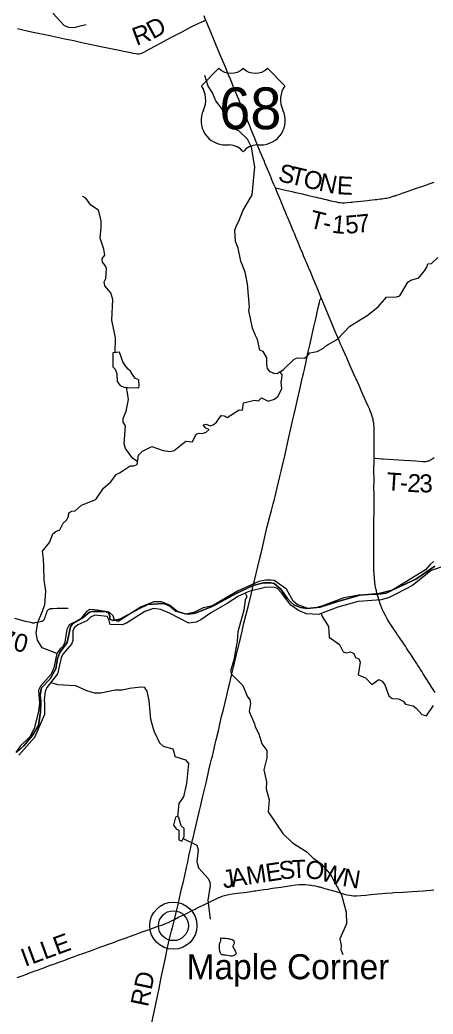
# Model space of a CAD drawing. Extents: x 1410790 to 1770854, y 448063 to 770588.
# Drawn here: x 1569641 to 1576526, y 587397 to 603957 of the extents above; entities that cross this region are included whole.
import ezdxf

# ---------------------------------------------------------------- set-up
doc = ezdxf.new("R2010")
doc.units = 0
for name, color, linetype in [('GM_X_County_Road', 7, 'Continuous'), ('GM_X_County_Road_Text', 7, 'Continuous'), ('GM_X_Major_River', 7, 'Continuous'), ('GM_X_Minor_Lake', 7, 'Continuous'), ('GM_X_Minor_River', 7, 'Continuous'), ('GM_X_Township', 7, 'Continuous'), ('GM_X_Township_Road', 7, 'Continuous'), ('GM_X_Township_Road_Text', 7, 'Continuous'), ('GM_X_Unincorporated', 7, 'Continuous'), ('GM_X_Unincorporated_Location', 7, 'Continuous'), ('GM_X_Unincorporated_Text', 7, 'Continuous'), ('GM_X_US_Location', 7, 'Continuous'), ('GM_X_US_Route', 7, 'Continuous'), ('GM_X_US_Shield', 7, 'Continuous')]:
    doc.layers.add(name, color=color, linetype=linetype)

msp = doc.modelspace()

# ---------------------------------------------------------------- linework, layer by layer
at = {"layer": 'GM_X_County_Road'}
for points in [[(1573528, 594535), (1573554, 594641), (1573605, 594855), (1573640, 594991), (1573660, 595077), (1573693, 595221), (1573724, 595348), (1573764, 595520), (1573806, 595684), (1573832, 595785), (1573861, 595899), (1573881, 595975), (1573892, 596020), (1573927, 596162), (1573971, 596353), (1573992, 596443), (1574014, 596536), (1574059, 596721), (1574123, 597007), (1574154, 597154), (1574189, 597303), (1574210, 597389), (1574232, 597485), (1574265, 597636), (1574298, 597779), (1574350, 598006), (1574364, 598067), (1574381, 598136), (1574412, 598270), (1574430, 598350), (1574447, 598431), (1574475, 598559), (1574518, 598744), (1574540, 598843), (1574555, 598910), (1574571, 598980), (1574586, 599051), (1574589, 599064), (1574606, 599140), (1574617, 599188), (1574631, 599252), (1574641, 599290), (1574645, 599300), (1574648, 599308), (1574661, 599330)], [(1572217, 588976), (1572255, 589133), (1572271, 589199), (1572283, 589252), (1572336, 589482), (1572361, 589584), (1572389, 589705), (1572419, 589840), (1572437, 589926), (1572457, 590029), (1572473, 590101), (1572482, 590142), (1572490, 590176), (1572519, 590301), (1572533, 590355), (1572552, 590434), (1572581, 590552), (1572636, 590788), (1572656, 590878), (1572684, 591006), (1572744, 591251), (1572774, 591378), (1572792, 591462), (1572813, 591554), (1572835, 591643), (1572848, 591694), (1572896, 591899), (1572912, 591966), (1572948, 592116), (1572974, 592227), (1573003, 592352), (1573031, 592473), (1573087, 592706), (1573112, 592807), (1573137, 592915), (1573173, 593066), (1573205, 593197), (1573245, 593363), (1573300, 593593), (1573315, 593656), (1573354, 593823), (1573369, 593886), (1573407, 594036), (1573448, 594205), (1573492, 594386), (1573528, 594535)], [(1572217, 588976), (1572238, 588988), (1572258, 588998), (1572284, 589012), (1572355, 589047), (1572426, 589081), (1572488, 589111), (1572521, 589126), (1572559, 589144), (1572580, 589155), (1572603, 589166), (1572726, 589227), (1572788, 589258), (1572838, 589283), (1572876, 589302), (1572888, 589307), (1572911, 589319), (1572934, 589329), (1572946, 589335), (1572976, 589347), (1573013, 589360), (1573051, 589371), (1573099, 589383), (1573147, 589393), (1573183, 589398), (1573264, 589410), (1573372, 589423), (1573462, 589436), (1573543, 589448), (1573553, 589450), (1573572, 589453), (1573631, 589461), (1573705, 589472), (1573770, 589481), (1573816, 589487), (1573851, 589493), (1573987, 589514), (1574159, 589540), (1574234, 589549), (1574293, 589554), (1574346, 589556), (1574396, 589555), (1574445, 589552), (1574484, 589547), (1574494, 589545), (1574517, 589542), (1574565, 589532), (1574603, 589523), (1574616, 589520), (1574638, 589515), (1574721, 589492), (1574765, 589480), (1574781, 589475), (1574828, 589461), (1574910, 589437), (1574960, 589422), (1575045, 589397), (1575089, 589386), (1575137, 589376), (1575166, 589372), (1575202, 589369), (1575247, 589369), (1575319, 589372), (1575407, 589380), (1575488, 589388), (1575603, 589399), (1575674, 589405), (1575730, 589410), (1575844, 589419), (1575867, 589421), (1576021, 589431), (1576175, 589441), (1576368, 589453), (1576424, 589457), (1576492, 589463), (1576537, 589470)], [(1569599, 588007), (1569679, 588037), (1569740, 588059), (1569777, 588072), (1569820, 588088), (1569913, 588122), (1569953, 588136), (1569977, 588145), (1570005, 588155), (1570038, 588168), (1570081, 588185), (1570118, 588199), (1570164, 588216), (1570188, 588225), (1570253, 588248), (1570290, 588261), (1570340, 588279), (1570361, 588287), (1570389, 588297), (1570459, 588324), (1570520, 588347), (1570635, 588388), (1570672, 588401), (1570833, 588458), (1570974, 588510), (1571024, 588528), (1571061, 588541), (1571101, 588556), (1571199, 588592), (1571279, 588622), (1571312, 588635), (1571427, 588675), (1571442, 588681), (1571470, 588690), (1571581, 588730), (1571664, 588760), (1571745, 588789), (1571831, 588819), (1571868, 588833), (1571945, 588860), (1572016, 588886), (1572035, 588892), (1572095, 588916), (1572116, 588925), (1572158, 588944), (1572217, 588976)], [(1571481, 585543), (1571507, 585661), (1571561, 585919), (1571597, 586089), (1571640, 586288), (1571674, 586448), (1571687, 586509), (1571756, 586843), (1571805, 587077), (1571836, 587228), (1571874, 587408), (1571928, 587669), (1571960, 587823), (1571998, 588006), (1572061, 588308), (1572103, 588507), (1572134, 588649), (1572167, 588786), (1572187, 588861), (1572199, 588908), (1572217, 588976)]]:
    msp.add_lwpolyline(points, dxfattribs=at)
at = {"layer": 'GM_X_Major_River'}
for points in [[(1576471, 594881), (1576397, 594797), (1575812, 594437), (1575737, 594404), (1575608, 594387), (1575291, 594375), (1575037, 594330), (1574671, 594194), (1574566, 594165), (1574441, 594153), (1574262, 594222), (1574197, 594277), (1574085, 594473), (1573876, 594620), (1573822, 594627), (1573741, 594627), (1573622, 594604), (1573269, 594441), (1572905, 594231), (1572830, 594190), (1572693, 594164), (1572549, 594093), (1572410, 594058), (1572266, 594105), (1572136, 594208), (1572001, 594264), (1571872, 594265), (1571662, 594183), (1571279, 593939), (1571219, 593961), (1571195, 594031), (1571128, 594091), (1570928, 594128), (1570878, 594133), (1570806, 594139), (1570755, 594110), (1570647, 593968), (1570461, 593882), (1570423, 593804), (1570388, 593595), (1570362, 593525), (1570307, 593476), (1570257, 593401), (1570207, 593165), (1570161, 593058), (1569983, 592857), (1569954, 592794), (1569967, 592575), (1569950, 592441), (1569930, 592347), (1569877, 592153), (1569810, 592018), (1569645, 591860), (1569573, 591753)], [(1576754, 594876), (1576495, 594786), (1576184, 594535), (1575906, 594393), (1575782, 594333), (1575659, 594300), (1575279, 594271), (1574941, 594174), (1574619, 594055), (1574419, 594064), (1574282, 594119), (1574153, 594210), (1573999, 594414), (1573935, 594484), (1573865, 594508), (1573730, 594501), (1573458, 594437), (1573284, 594361), (1573096, 594239), (1573019, 594192), (1572836, 594088), (1572656, 593962), (1572579, 593923), (1572456, 593910), (1572135, 594074), (1571990, 594138), (1571870, 594152), (1571724, 594104), (1571415, 593910), (1571346, 593882), (1571147, 593886), (1571131, 593955), (1571098, 594022), (1570890, 594043), (1570819, 594008), (1570755, 593947), (1570609, 593880), (1570544, 593834), (1570523, 593782), (1570525, 593621), (1570501, 593560), (1570359, 593394), (1570330, 593331), (1570269, 593063), (1570091, 592839), (1570060, 592769), (1570048, 592629), (1570051, 592579), (1570051, 592386), (1569883, 592003), (1569622, 591708)], [(1576535, 594937), (1576470, 594880)]]:
    msp.add_lwpolyline(points, dxfattribs=at)
at = {"layer": 'GM_X_Minor_Lake'}
for points in [[(1571626, 597863), (1571624, 597960), (1571568, 597983), (1571538, 598015), (1571519, 598052), (1571486, 598106), (1571448, 598137), (1571399, 598196), (1571356, 598263), (1571337, 598330), (1571301, 598424), (1571190, 598412), (1571190, 598176), (1571230, 598137), (1571259, 598064), (1571264, 597932), (1571311, 597865), (1571371, 597840), (1571435, 597835)], [(1571435, 597835), (1571621, 597827), (1571626, 597863)], [(1572235, 590679), (1572198, 590547), (1572245, 590484), (1572287, 590461), (1572292, 590362), (1572289, 590300), (1572341, 590279), (1572379, 590358), (1572381, 590491), (1572328, 590534), (1572308, 590609), (1572289, 590673)], [(1572289, 590673), (1572275, 590685), (1572262, 590691), (1572235, 590679)], [(1572992, 588669), (1573020, 588665), (1573038, 588662), (1573068, 588660), (1573094, 588658), (1573114, 588658), (1573126, 588654), (1573140, 588650), (1573154, 588648), (1573178, 588641), (1573194, 588629), (1573204, 588613), (1573210, 588601), (1573210, 588585), (1573206, 588565), (1573200, 588551), (1573194, 588541), (1573189, 588527), (1573189, 588517), (1573195, 588507), (1573207, 588491), (1573217, 588466), (1573227, 588452), (1573233, 588436), (1573241, 588424), (1573243, 588410), (1573237, 588394), (1573227, 588384), (1573217, 588378), (1573200, 588370), (1573190, 588366), (1573174, 588364), (1573152, 588365), (1573128, 588369), (1573098, 588373), (1573066, 588377), (1573038, 588379), (1573022, 588382), (1573008, 588386), (1572992, 588402), (1572984, 588412), (1572972, 588446), (1572970, 588456), (1572968, 588468), (1572966, 588480), (1572966, 588494), (1572965, 588508), (1572965, 588522), (1572965, 588537), (1572965, 588547), (1572967, 588557), (1572967, 588567), (1572973, 588581), (1572979, 588595), (1572983, 588605), (1572989, 588617), (1572992, 588669)]]:
    msp.add_lwpolyline(points, dxfattribs=at)
at = {"layer": 'GM_X_Minor_River'}
for points in [[(1570190, 604068), (1570379, 603864), (1570449, 603835), (1570551, 603833), (1570668, 603861), (1570745, 603880)], [(1570035, 594973), (1570021, 595110), (1570134, 595250), (1570189, 595396), (1570239, 595437), (1570306, 595464), (1570360, 595575), (1570417, 595625), (1570454, 595688), (1570457, 595744), (1570508, 595775), (1570560, 595780), (1570666, 595875), (1570906, 595969), (1571034, 596157), (1571156, 596264), (1571246, 596384), (1571299, 596415), (1571363, 596454), (1571477, 596531), (1571541, 596530), (1571594, 596549), (1571618, 596707), (1571686, 596772), (1571841, 596853), (1572029, 596786), (1572143, 596766), (1572213, 596787), (1572406, 596938), (1572518, 596932), (1572577, 597057), (1572629, 597074), (1572681, 597067), (1572744, 597090), (1572794, 597136), (1572739, 597155), (1572694, 597212), (1572744, 597223), (1572810, 597196), (1572860, 597211), (1572917, 597256), (1572993, 597367), (1573043, 597364), (1573097, 597337), (1573295, 597464), (1573349, 597459), (1573367, 597579), (1573440, 597596), (1573551, 597622), (1573617, 597611), (1573669, 597660), (1573779, 597606), (1573886, 597640), (1573937, 597687), (1574005, 597811), (1573997, 597927), (1574008, 597979), (1574011, 598043), (1573980, 598096), (1573929, 598063), (1573871, 598066), (1573813, 598093), (1573768, 598152), (1573753, 598216), (1573755, 598328), (1573697, 598433), (1573641, 598458), (1573602, 598634), (1573565, 598700), (1573517, 598822), (1573458, 599115), (1573465, 599173), (1573431, 599563), (1573397, 599758), (1573325, 599938), (1573277, 600155), (1573233, 600268), (1573224, 600455), (1573253, 600530), (1573287, 600604), (1573354, 600775), (1573511, 601043), (1573555, 601512), (1573502, 601837), (1573436, 601971), (1573288, 602112), (1573235, 602133), (1573186, 602198), (1573065, 602290), (1573037, 602431), (1573002, 602487), (1572904, 602609), (1572848, 602745), (1572780, 602854), (1572723, 603030)], [(1571228, 598416), (1571233, 598664), (1571172, 598954), (1571192, 599298), (1571157, 599409), (1571055, 599527), (1571046, 599592), (1571073, 599647), (1571086, 599816), (1571065, 599868), (1571018, 599923), (1571015, 599983), (1571054, 600041), (1571038, 600141), (1570978, 600321), (1570998, 600499), (1570994, 600617), (1570952, 600790), (1570823, 600869), (1570743, 600988), (1570692, 601015), (1570682, 601020)], [(1573980, 598096), (1574036, 598133), (1574212, 598304), (1574264, 598327), (1574383, 598325), (1574433, 598359), (1574470, 598410), (1574593, 598432), (1574700, 598488), (1574751, 598536), (1574931, 598639), (1575141, 598854), (1575425, 599035), (1575610, 599179), (1575747, 599339), (1575916, 599344), (1575970, 599359), (1576104, 599587), (1576155, 599622), (1576288, 599662), (1576380, 599775), (1576419, 599838), (1576436, 599892), (1576498, 599899), (1576606, 600002)], [(1571602, 596603), (1571521, 596652), (1571400, 596817), (1571379, 596897), (1571402, 597196), (1571363, 597256), (1571362, 597317), (1571412, 597440), (1571450, 597632), (1571436, 597744), (1571415, 597836)], [(1570257, 593401), (1570015, 593496), (1569934, 593625), (1569915, 593747), (1569940, 593919), (1570014, 594098), (1570057, 594215), (1570076, 594440), (1570044, 594629), (1570042, 594854), (1570035, 594973)], [(1573396, 594410), (1573424, 594351), (1573394, 594292), (1573375, 594128), (1573275, 593765), (1573263, 593607), (1573207, 593297), (1573149, 593112), (1573172, 593056), (1573358, 592871), (1573426, 592691), (1573473, 592631), (1573484, 592571), (1573461, 592437), (1573553, 592232), (1573559, 592180), (1573625, 592066), (1573670, 591897), (1573755, 591790), (1573756, 591736), (1573755, 591664), (1573706, 591465), (1573748, 591269), (1573744, 591151), (1573792, 590965), (1573780, 590767), (1574022, 590408), (1574181, 590250), (1574421, 590098), (1574526, 589993), (1574590, 589954), (1574653, 589908), (1574815, 589724), (1574998, 589382), (1575080, 589098), (1575082, 588901), (1574971, 588649), (1574996, 588538), (1574987, 588476), (1575021, 588389)], [(1574662, 594071), (1574679, 594019), (1574781, 593856), (1574796, 593677), (1574969, 593555), (1575025, 593433), (1575084, 593414), (1575147, 593429), (1575204, 593403), (1575233, 593338), (1575289, 593315), (1575312, 593262), (1575279, 593050), (1575402, 592999), (1575506, 592885), (1575622, 592972), (1575679, 592941), (1575722, 592882), (1575786, 592698), (1575846, 592652), (1575952, 592650), (1576025, 592612), (1576066, 592561), (1576194, 592530), (1576245, 592494), (1576339, 592386), (1576418, 592364), (1576532, 592536)], [(1570155, 592919), (1570269, 592889), (1570567, 592872), (1570754, 592787), (1570879, 592750), (1570989, 592750), (1571231, 592800), (1571345, 592801), (1571468, 592829), (1571656, 592848), (1571712, 592841), (1571759, 592776), (1571788, 592617), (1571819, 592311), (1571873, 592115), (1571967, 591916), (1572030, 591861), (1572189, 591817), (1572214, 591744), (1572223, 591690), (1572402, 591631), (1572449, 591572), (1572419, 591238), (1572367, 591018), (1572290, 590908), (1572267, 590689)], [(1572362, 590323), (1572588, 590209), (1572610, 590132), (1572588, 589940), (1572618, 589833), (1572772, 589659), (1572805, 589598), (1572814, 589540), (1572773, 589296), (1572810, 588978)]]:
    msp.add_lwpolyline(points, dxfattribs=at)
at = {"layer": 'GM_X_Township'}
for points in [[(1569593, 591763), (1569705, 591867), (1569844, 592030), (1569954, 592204), (1569986, 592431), (1569989, 592601), (1569980, 592715), (1570003, 592830), (1570146, 592983), (1570238, 593149), (1570267, 593317), (1570308, 593421), (1570432, 593585), (1570484, 593849), (1570525, 593901), (1570698, 594002), (1570801, 594091), (1570851, 594105), (1571064, 594103), (1571118, 594079), (1571140, 594027), (1571139, 593976), (1571197, 593952), (1571308, 593977), (1571636, 594153), (1571775, 594218), (1572032, 594238), (1572134, 594195), (1572238, 594110), (1572394, 594067), (1572452, 594058), (1572569, 594075), (1572856, 594194), (1573257, 594411), (1573519, 594533), (1573530, 594536), (1573702, 594580), (1573817, 594579), (1573879, 594567), (1573988, 594478), (1574102, 594318), (1574151, 594266), (1574207, 594217), (1574315, 594170), (1574429, 594153), (1574646, 594173), (1574940, 594269), (1575312, 594377), (1575567, 594399), (1575629, 594404), (1575842, 594461), (1576237, 594642), (1576556, 594859)], [(1576556, 594859), (1576237, 594642), (1575842, 594461), (1575629, 594404), (1575567, 594399), (1575312, 594377), (1574940, 594269), (1574646, 594173), (1574429, 594153), (1574315, 594170), (1574207, 594217), (1574151, 594266), (1574102, 594318), (1573988, 594478), (1573879, 594567), (1573817, 594579), (1573702, 594580), (1573530, 594536), (1573519, 594533), (1573257, 594411), (1572856, 594194), (1572569, 594075), (1572452, 594058), (1572394, 594067), (1572238, 594110), (1572134, 594195), (1572032, 594238), (1571775, 594218), (1571636, 594153), (1571308, 593977), (1571197, 593952), (1571139, 593976), (1571140, 594027), (1571118, 594079), (1571064, 594103), (1570851, 594105), (1570801, 594091), (1570698, 594002), (1570525, 593901), (1570484, 593849), (1570432, 593585), (1570308, 593421), (1570267, 593317), (1570238, 593149), (1570146, 592983), (1570003, 592830), (1569980, 592715), (1569989, 592601), (1569986, 592431), (1569954, 592204), (1569844, 592030), (1569705, 591867), (1569593, 591763)]]:
    msp.add_lwpolyline(points, dxfattribs=at)
at = {"layer": 'GM_X_Township_Road'}
for points in [[(1569602, 603813), (1569691, 603794), (1569837, 603760), (1570055, 603714), (1570141, 603696), (1570393, 603641), (1570538, 603613), (1570676, 603583), (1570833, 603549), (1571016, 603511), (1571186, 603476), (1571484, 603412), (1571526, 603403), (1571571, 603395), (1571598, 603393), (1571628, 603394), (1571655, 603400), (1571683, 603410), (1571716, 603425), (1571794, 603468), (1571911, 603533), (1572045, 603603), (1572158, 603662), (1572344, 603760), (1572495, 603839), (1572592, 603887), (1572633, 603907), (1572662, 603921), (1572698, 603938), (1572736, 603956)], [(1573898, 601158), (1573949, 601147), (1574016, 601133), (1574122, 601109), (1574171, 601098), (1574233, 601084), (1574266, 601077), (1574297, 601070), (1574350, 601058), (1574405, 601045), (1574433, 601039), (1574473, 601029), (1574520, 601018), (1574577, 601003), (1574619, 600993), (1574648, 600986), (1574711, 600971), (1574746, 600963), (1574762, 600959), (1574820, 600946), (1574877, 600933), (1574919, 600924), (1574934, 600920), (1574958, 600916), (1574978, 600913), (1575012, 600911), (1575031, 600910), (1575050, 600911), (1575093, 600913), (1575148, 600919), (1575177, 600923), (1575200, 600925), (1575265, 600932), (1575324, 600938), (1575432, 600951), (1575468, 600955), (1575512, 600960), (1575561, 600965), (1575591, 600968), (1575613, 600971), (1575646, 600975), (1575674, 600978), (1575707, 600983), (1575727, 600986), (1575752, 600990), (1575776, 600995), (1575799, 601001), (1575834, 601011), (1575847, 601015), (1575862, 601019), (1575877, 601024), (1575892, 601029), (1575911, 601035), (1575932, 601042), (1575959, 601051), (1575982, 601059), (1576010, 601069), (1576096, 601099), (1576216, 601141), (1576405, 601206), (1576460, 601226), (1576543, 601256)], [(1575543, 596660), (1575563, 596658), (1575671, 596646), (1575696, 596644), (1576038, 596622), (1576238, 596611), (1576353, 596604), (1576386, 596603), (1576406, 596604), (1576428, 596607), (1576443, 596611), (1576455, 596615), (1576469, 596620), (1576484, 596628), (1576498, 596636), (1576511, 596645), (1576541, 596670)], [(1569554, 593990), (1569732, 593944), (1569818, 593923), (1569833, 593920), (1569842, 593918), (1569852, 593917), (1569862, 593916), (1569873, 593916), (1569885, 593917), (1569896, 593918), (1569922, 593923), (1569979, 593935), (1570002, 593941), (1570014, 593945), (1570023, 593948), (1570031, 593953), (1570039, 593958), (1570043, 593962), (1570047, 593968), (1570050, 593974), (1570053, 593983), (1570057, 593993), (1570061, 594004), (1570065, 594015), (1570069, 594026), (1570075, 594044), (1570082, 594063), (1570086, 594077), (1570090, 594088), (1570093, 594099), (1570096, 594108), (1570099, 594115), (1570102, 594120), (1570105, 594125), (1570111, 594130), (1570116, 594135), (1570121, 594139), (1570128, 594143), (1570137, 594146), (1570147, 594150), (1570157, 594152), (1570167, 594153), (1570173, 594154), (1570178, 594154), (1570190, 594155), (1570263, 594157), (1570354, 594159), (1570445, 594160)]]:
    msp.add_lwpolyline(points, dxfattribs=at)
at = {"layer": 'GM_X_Unincorporated'}
for radius in [393, 249]:
    msp.add_circle((1572199, 588870), radius, dxfattribs=at)
at = {"layer": 'GM_X_Unincorporated_Location'}
msp.add_line((1572199, 588870), (1572199, 588870), dxfattribs=at)
at = {"layer": 'GM_X_US_Route'}
for points in [[(1575540, 595485), (1575540, 595517), (1575541, 595638), (1575542, 595733), (1575542, 595782), (1575542, 595858), (1575542, 595900), (1575542, 595956), (1575542, 596015), (1575542, 596051), (1575542, 596077), (1575541, 596153), (1575541, 596200), (1575542, 596242), (1575542, 596291), (1575542, 596334), (1575541, 596415), (1575541, 596480), (1575542, 596598), (1575542, 596614), (1575542, 596634), (1575543, 596660), (1575544, 596742), (1575544, 596778), (1575544, 596804), (1575544, 596826), (1575544, 596846), (1575544, 596869), (1575544, 596888), (1575545, 596967), (1575544, 597062), (1575543, 597095), (1575542, 597166), (1575539, 597222), (1575537, 597241), (1575534, 597258), (1575530, 597283), (1575525, 597306), (1575517, 597337), (1575507, 597372), (1575493, 597410), (1575485, 597430), (1575479, 597445), (1575464, 597479), (1575450, 597512), (1575413, 597594), (1575362, 597709), (1575327, 597787), (1575297, 597856), (1575253, 597955), (1575240, 597982), (1575228, 598009), (1575206, 598059), (1575162, 598158), (1575140, 598206), (1575086, 598329), (1575054, 598401), (1575026, 598464), (1575000, 598524), (1574985, 598557), (1574966, 598602), (1574954, 598629), (1574937, 598668), (1574891, 598777), (1574832, 598919), (1574789, 599022), (1574738, 599144), (1574668, 599314), (1574661, 599330), (1574593, 599493), (1574528, 599652), (1574488, 599749), (1574456, 599824), (1574421, 599906), (1574402, 599951), (1574396, 599966), (1574369, 600030), (1574354, 600066), (1574319, 600151), (1574279, 600248), (1574256, 600302), (1574241, 600338), (1574221, 600387), (1574200, 600435), (1574180, 600483), (1574153, 600546), (1574139, 600580), (1574110, 600649), (1574091, 600695), (1574066, 600755), (1574041, 600816), (1574022, 600861), (1574006, 600901), (1573988, 600943), (1573959, 601012), (1573941, 601058), (1573924, 601097), (1573898, 601158), (1573893, 601169), (1573874, 601215), (1573841, 601293), (1573827, 601326), (1573809, 601369), (1573725, 601571), (1573715, 601596), (1573685, 601668), (1573672, 601699), (1573647, 601759), (1573625, 601814), (1573608, 601853), (1573549, 601999), (1573500, 602117), (1573471, 602187), (1573449, 602241), (1573420, 602311), (1573411, 602336), (1573400, 602363), (1573356, 602469), (1573326, 602540), (1573302, 602596), (1573288, 602629), (1573267, 602681), (1573229, 602771), (1573213, 602811), (1573194, 602856), (1573170, 602913), (1573154, 602953), (1573132, 603007), (1573125, 603025), (1573066, 603168), (1572973, 603389), (1572907, 603550), (1572820, 603755), (1572749, 603925), (1572736, 603956), (1572710, 604022)], [(1575562, 594543), (1575555, 594590), (1575548, 594655), (1575547, 594665), (1575543, 594727), (1575541, 594799), (1575541, 594960), (1575541, 595071), (1575541, 595190), (1575541, 595271), (1575540, 595402), (1575540, 595445), (1575540, 595485)], [(1575677, 594148), (1575672, 594159), (1575655, 594202), (1575645, 594229), (1575626, 594285), (1575608, 594341), (1575608, 594342), (1575590, 594407), (1575581, 594445), (1575568, 594503), (1575562, 594538), (1575562, 594543)], [(1576558, 592755), (1576507, 592836), (1576472, 592891), (1576410, 592988), (1576361, 593065), (1576342, 593096), (1576316, 593138), (1576293, 593174), (1576274, 593204), (1576251, 593240), (1576233, 593268), (1576212, 593301), (1576178, 593353), (1576147, 593399), (1576129, 593427), (1576084, 593495), (1576064, 593525), (1576038, 593563), (1575964, 593672), (1575935, 593715), (1575911, 593751), (1575849, 593843), (1575826, 593875), (1575799, 593916), (1575766, 593972), (1575731, 594035), (1575699, 594099), (1575685, 594131), (1575677, 594148)]]:
    msp.add_lwpolyline(points, dxfattribs=at)
at = {"layer": 'GM_X_US_Shield'}
for p, q in [((1572955, 603151), (1572665, 602861)), ((1574057, 602861), (1573767, 603151)), ((1573071, 601875), (1573129, 601875)), ((1573593, 601875), (1573651, 601875))]:
    msp.add_line(p, q, dxfattribs=at)
for centre, radius, start, end in [((1573158, 603358), 290, 225.573, 314.427), ((1573564, 603358), 290, 225.573, 314.427), ((1572332, 602628), 406, 334.5471, 35.0009), ((1574390, 602628), 406, 144.9991, 205.4529), ((1573066, 602281), 406, 154.8319, 270.6383), ((1573656, 602281), 406, 269.3617, 25.1681), ((1573129, 601584), 290, 36.8699, 90), ((1573593, 601584), 290, 90, 143.1301)]:
    msp.add_arc(centre, radius, start, end, dxfattribs=at)

# ---------------------------------------------------------------- texts
at = {"layer": 'GM_X_County_Road_Text'}
for s, rotation, p in [('M', 8.6096, (1573436, 589551)), ('E', 8.5816, (1573758, 589599)), ('S', 7.9944, (1573979, 589633)), ('T', 2.9454, (1574173, 589660)), ('O', 351.1677, (1574380, 589673)), ('W', 344.4403, (1574632, 589634)), ('J', 8.6111, (1573036, 589490)), ('A', 8.6077, (1573175, 589511)), ('N', 350.5162, (1575001, 589533)), ('E', 20.2525, (1570264, 588381)), ('L', 20.2486, (1570053, 588303)), ('I', 20.2472, (1569727, 588183)), ('L', 20.2525, (1569843, 588225)), ('RD', 78.2123, (1571775, 587506))]:
    msp.add_text(s, height=300, rotation=rotation, dxfattribs=at).set_placement(p)
at = {"layer": 'GM_X_Township_Road_Text'}
for s, rotation, p in [('D', 28.7349, (1571856, 603628)), ('R', 20.504, (1571583, 603523)), ('S', 346.8223, (1573928, 601276)), ('T', 346.8213, (1574125, 601230)), ('O', 346.8262, (1574344, 601179)), ('N', 347.9743, (1574607, 601117)), ('E', 357.0864, (1574917, 601055)), ('T', 346.3099, (1574448, 600501)), ('1', 354.5126, (1574832, 600412)), ('5', 4.5371, (1575073, 600394)), ('7', 6.1146, (1575266, 600409)), ('-', 346.7717, (1574669, 600447)), ('T', 356.0713, (1575741, 596123)), ('2', 356.2908, (1576089, 596099)), ('3', 0.7141, (1576299, 596086)), ('-', 356.112, (1575965, 596107)), ('T-70', 345.7946, (1568932, 593612))]:
    msp.add_text(s, height=300, rotation=rotation, dxfattribs=at).set_placement(p)
at = {"layer": 'GM_X_Unincorporated_Text'}
msp.add_text('Maple Corner', height=417, rotation=0, dxfattribs=at).set_placement((1572419, 587978))
at = {"layer": 'GM_X_US_Location'}
for s in ['0', '/']:
    msp.add_text(s, height=1, dxfattribs=at).set_placement((1573361, 602478))
msp.add_text('68', height=1, rotation=0, dxfattribs=at).set_placement((1573154, 602271))
at = {"layer": 'GM_X_US_Shield'}
msp.add_text('68', height=696.1, dxfattribs=at).set_placement((1572963, 602136))

doc.saveas('drawing.dxf')
